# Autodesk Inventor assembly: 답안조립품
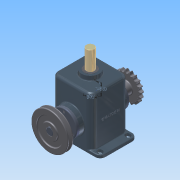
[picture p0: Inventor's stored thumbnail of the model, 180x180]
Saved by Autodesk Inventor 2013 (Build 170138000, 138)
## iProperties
Created: 2015-03
Part Number: 답안조립품
Document SubType Name: Assembly
Designer: Administrator
Mass: 8579.28 g
Surface Area: 4386.42 cm^2
Volume: 1982.54 cm^3
Density: 4.32742 g/cm^3
Author: Administrator
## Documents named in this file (15)
- C:\Documents and Settings\Administrator\바탕 화면\350305V1032\답안조립품.iam
- C:\Documents and Settings\Administrator\바탕 화면\350305V1032\본체.ipt
- C:\Documents and Settings\Administrator\바탕 화면\350305V1032\베어링 6205.ipt
- C:\Documents and Settings\Administrator\바탕 화면\350305V1032\커버.ipt
- C:\Documents and Settings\Administrator\바탕 화면\350305V1032\M4x0.5.ipt
- C:\Documents and Settings\Administrator\바탕 화면\350305V1032\편심축.ipt
- C:\Documents and Settings\Administrator\바탕 화면\350305V1032\멈춤링.ipt
- C:\Documents and Settings\Administrator\바탕 화면\350305V1032\오일실.ipt
- C:\Documents and Settings\Administrator\바탕 화면\350305V1032\체인 스프로킷.ipt
- C:\Documents and Settings\Administrator\바탕 화면\350305V1032\키 8x8.ipt
- C:\Documents and Settings\Administrator\바탕 화면\350305V1032\V-벨트풀리.ipt
- C:\Documents and Settings\Administrator\바탕 화면\350305V1032\멈춤나사 M5x0.5.ipt
- C:\Documents and Settings\Administrator\바탕 화면\350305V1032\부시.ipt
- C:\Documents and Settings\Administrator\바탕 화면\350305V1032\슬라이드.ipt
- C:\Documents and Settings\Administrator\바탕 화면\350305V1032\7-가변스프링.ipt
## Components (9 placed, 4 different names)
1. 5-체인 스프로킷:1 — 플러쉬:1, 각도:3
2. V-벨트풀리:1 — 플러쉬:2, 각도:4
3. 7-가변스프링:1
4. M4x0.5:1
5. M4x0.5:3
6. M4x0.5:4
7. M4x0.5:2
8. M4x0.5:5
9. M4x0.5:6
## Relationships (4: Flush 2, Angle 2)
- 플러쉬:1 [Flush]: 5-체인 스프로킷:1
- 각도:3 [Angle]: 5-체인 스프로킷:1
- 플러쉬:2 [Flush]: V-벨트풀리:1
- 각도:4 [Angle]: V-벨트풀리:1
